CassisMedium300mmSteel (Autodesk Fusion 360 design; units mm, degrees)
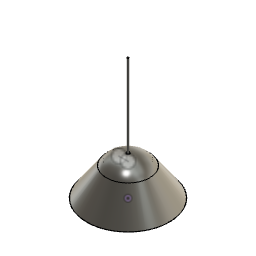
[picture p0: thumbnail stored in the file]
sketch "Sketch1" plane through (0, 0, 0) normal (0, 1, 0) x axis (1, 0, 0)
  line L1 (-5, -140) -> (0, -140)
  line L2 (-77.9023, -102.6) -> (-150, 0)
  line L3 (0, 0) -> (0, -140)
  line L4 (-150, 0) -> (0, 0)
  arc A1 centre (-5.9016, -52.0046) radius 88 clockwise from (-5, -140) to (-77.9023, -102.6)
  point P1 (0, 0)
  point P4 (-150, 0)
  point P2 (0, -140)
  point P7 (0, 0)
  point P3 (-5, -140)
  point P5 (-77.9023, -102.6)
  horizontal L1
  horizontal P1 P4
  vertical P1 P2
  coincident P1 P7
  tangent L2 A1
  dimension "d1" distance P2 P3 = 5
  dimension "d2" distance P1 L1 = 140
  dimension "d3" distance P1 P4 = 150
  dimension "d39" distance P5 L4 = 102.6
  dimension "d40" radius A1 = 88
revolve "Revolve1" sketch "Sketch1" AlongAngle 360
shell "Shell1" innerThickness 1.5
fillet "Fillet1" radius 0.5
sketch "Sketch2" plane through (0, 0, 0) normal (0, 1, 0) x axis (1, 0, 0)
  line L1 (-32.2676, -115) -> (0, -115)
  point P1 (0, 0)
  horizontal L1
  dimension "d14" distance P1 L1 = 115
work_plane "WorkPlane1" AlongDistance 70
sketch "Sketch4" plane through (0, 0, 115) normal (0, 0, 1) x axis (1, 0, 0)
  circle C1 centre (0, 0) radius 43.7102
  point P1 (0, 0)
  point P2 (0, 0)
  coincident P1 P2
extrude "Extrude2" new body sketch "Sketch4" against normal blind 12 taper -20
sketch "Sketch8" plane through (0, 0, 115) normal (0, 0, 1) x axis (-1, 0, 0)
  circle C1 centre (0, 0) radius 43.7102
  circle C2 centre (0, 0) radius 62.5
  point P1 (0, 0)
  point P3 (0, 0)
  coincident P1 P3
  dimension "d41" diameter C2 = 125
extrude "Extrude8" new body sketch "Sketch8" along normal blind 1
sketch "Sketch5" plane through (0, 0, 103) normal (0, 0, -1) x axis (1, 0, 0)
  circle C1 centre (0, 0) radius 39.3425
  circle C2 centre (0, 0) radius 35.3425
  point P1 (0, 0)
  point P3 (0, 0)
  coincident P1 P3
  dimension "d19" distance C1 C2 = 4
extrude "Extrude3" cut sketch "Sketch5" profile of C2 against normal blind 10
extrude "Extrude4" new body of existing geometry blind 20
work_plane "WorkPlane2" AlongDistance -5
split "Split1"
fillet "Fillet2" radius 0.1
fillet "Fillet3" radius 0.4
sketch "Sketch6" plane through (0, 0, 140) normal (0, 0, 1) x axis (-1, 0, 0)
  circle C1 centre (0, 0) radius 5
  circle C2 centre (0, 0) radius 6
  point P1 (0, 0)
  point P3 (0, 0)
  coincident P1 P3
  dimension "d29" diameter C2 = 12
extrude "Extrude5" new body sketch "Sketch6" along normal blind 1.5
extrude "Extrude6" cut of existing geometry blind -1.5
sketch "Sketch7" plane through (0, 0, 115) normal (0, 0, 1) x axis (-1, 0, 0)
  circle C1 centre (0, 0) radius 43.7102
  circle C2 centre (0, 0) radius 3
  point P1 (0, 0)
  point P3 (0, 0)
  coincident P1 P3
  dimension "d34" diameter C2 = 6
extrude "Extrude7" new body sketch "Sketch7" profile of C2 along normal blind 323
fillet "Fillet4" radius 0.2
